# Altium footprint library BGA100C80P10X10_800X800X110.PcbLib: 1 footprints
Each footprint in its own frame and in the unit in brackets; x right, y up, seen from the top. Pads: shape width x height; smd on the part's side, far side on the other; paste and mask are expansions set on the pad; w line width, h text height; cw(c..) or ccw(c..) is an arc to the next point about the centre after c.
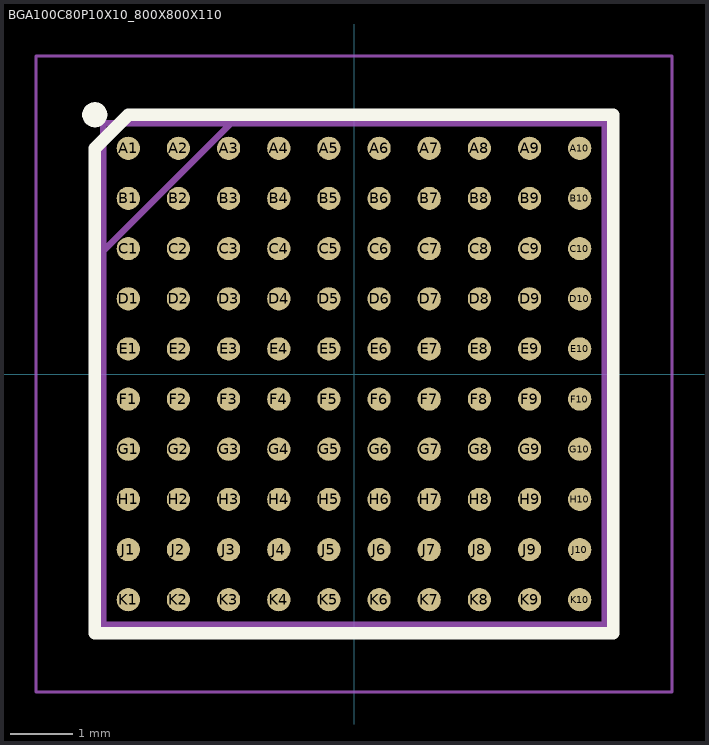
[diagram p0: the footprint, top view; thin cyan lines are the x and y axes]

## BGA100C80P10X10_800X800X110 [mm]
pads (100):
  round 0.37 smd: A1(-3.6,3.6) A2(-2.8,3.6) A3(-2,3.6) A4(-1.2,3.6) A5(-0.4,3.6) A6(0.4,3.6) A7(1.2,3.6) A8(2,3.6) A9(2.8,3.6) A10(3.6,3.6) B1(-3.6,2.8) B2(-2.8,2.8) B3(-2,2.8) B4(-1.2,2.8) B5(-0.4,2.8) B6(0.4,2.8) B7(1.2,2.8) B8(2,2.8) B9(2.8,2.8) B10(3.6,2.8) C1(-3.6,2) C2(-2.8,2) C3(-2,2) C4(-1.2,2) C5(-0.4,2) C6(0.4,2) C7(1.2,2) C8(2,2) C9(2.8,2) C10(3.6,2) D1(-3.6,1.2) D2(-2.8,1.2) D3(-2,1.2) D4(-1.2,1.2) D5(-0.4,1.2) D6(0.4,1.2) D7(1.2,1.2) D8(2,1.2) D9(2.8,1.2) D10(3.6,1.2) E1(-3.6,0.4) E2(-2.8,0.4) E3(-2,0.4) E4(-1.2,0.4) E5(-0.4,0.4) E6(0.4,0.4) E7(1.2,0.4) E8(2,0.4) E9(2.8,0.4) E10(3.6,0.4) F1(-3.6,-0.4) F2(-2.8,-0.4) F3(-2,-0.4) F4(-1.2,-0.4) F5(-0.4,-0.4) F6(0.4,-0.4) F7(1.2,-0.4) F8(2,-0.4) F9(2.8,-0.4) F10(3.6,-0.4) G1(-3.6,-1.2) G2(-2.8,-1.2) G3(-2,-1.2) G4(-1.2,-1.2) G5(-0.4,-1.2) G6(0.4,-1.2) G7(1.2,-1.2) G8(2,-1.2) G9(2.8,-1.2) G10(3.6,-1.2) H1(-3.6,-2) H2(-2.8,-2) H3(-2,-2) H4(-1.2,-2) H5(-0.4,-2) H6(0.4,-2) H7(1.2,-2) H8(2,-2) H9(2.8,-2) H10(3.6,-2) J1(-3.6,-2.8) J2(-2.8,-2.8) J3(-2,-2.8) J4(-1.2,-2.8) J5(-0.4,-2.8) J6(0.4,-2.8) J7(1.2,-2.8) J8(2,-2.8) J9(2.8,-2.8) J10(3.6,-2.8) K1(-3.6,-3.6) K2(-2.8,-3.6) K3(-2,-3.6) K4(-1.2,-3.6) K5(-0.4,-3.6) K6(0.4,-3.6) K7(1.2,-3.6) K8(2,-3.6) K9(2.8,-3.6) K10(3.6,-3.6)
Top Overlay:
  circle w0.2: c-4.135,4.135 r0.1
  lines w0.2: -4.135,-4.135 4.135,-4.135 4.135,4.135 -3.6,4.135 -4.135,3.6 -4.135,-4.135
Mechanical 15:
  lines w0.1: -4,1.962 -1.962,4 ; -4,-4 4,-4 4,4 -4,4 -4,-4
Mechanical 20:
  lines w0.05: -5.075,-5.075 5.075,-5.075 5.075,5.075 -5.075,5.075 -5.075,-5.075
